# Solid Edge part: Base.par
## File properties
Title: Base
Author: windows
Template: Iso Metric Part.par
Last saved by: windows
Revision: 21
Application: Solid Edge
Username: windows
Density: 886,000 kg/m^3
Accuracy: 0,990
Material: Polyethylene, low density
Face Style: Blue
Fill Style: ANSI34(Plastic)
Virtual Style: ANSI34(Plastic)
Grouping: Non-metals\Plastics
LibraryName: Materials
Coef. of Thermal Exp: 0.00016
Thermal Conductivity: 3.9
Specific Heat: 2219.0
Modulus of Elasticity: 144789897.0
Poisson's Ratio: 0.35
Yield Stress: 9652659.8
Ultimate Stress: 0.0
Elongation: 0.0
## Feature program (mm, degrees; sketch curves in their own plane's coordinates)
swept protrusion "Protrusion_1"
sketch for "ExtrudedCutout_1" plane through (0, 0, 0) normal (0, 0, 1) x-axis (1, 0, 0)
extrude "ExtrudedCutout_1" cut finite 36.5507 along -normal
sketch used by "Protrusion_1" plane through (148.6392, 0, 45.0365) normal (0.570057, 0, 0.821605) x-axis (0, 1, 0)
extrude "Protrusion_1" add finite 77.0756 along +normal
sketch for "ExtrudedCutout_2" plane through (157.5009, 0, 46.9978) normal (0, 0, -1) x-axis (0, -1, 0)
extrude "ExtrudedCutout_2" cut finite 108.6577 along -normal
sketch for "Protrusion_2" plane through (156.0857, 0, 46.9978) normal (0, 0, 1) x-axis (0, 1, 0)
  line (-5, -6.0857) -> (-5, 6.0857)
  line (-5, 6.0857) -> (5, 6.0857)
  line (5, 6.0857) -> (5, -6.0857)
  line (5, -6.0857) -> (-5, -6.0857)
extrude "Protrusion_2" add finite 23 along +normal
fillet "Round_1" radius 2
fillet "Round_2" radius 2
fillet "Round_3" radius 5
fillet "Round_4" radius 5
rib "Rib_1"  Thickness = 3 mm
fillet "Round_5" radius 1
sketch used by "Cutout_3" plane through (77.5395, 0, 57) normal (0, 0, 1) x-axis (0, 1, 0)
  line (-25, -23.8999) -> (25, -23.8999)
  line (25, -23.8999) -> (25, 26.1001)
  line (25, 26.1001) -> (-25, 26.1001)
  line (-25, 26.1001) -> (-25, -23.8999)
  line (-35.5538, 44.0098) -> (-15.5538, 44.0098)
  line (-15.5538, 44.0098) -> (-15.5538, 64.0098)
  line (-15.5538, 64.0098) -> (-35.5538, 64.0098)
  line (-35.5538, 64.0098) -> (-35.5538, 44.0098)
extrude "Cutout_3" cut finite 5 symmetric
sketch for "Cutout_4" plane through (76.0856, -50.2879, 25.7796) normal (0.036015, -0.999292, 0.0109) x-axis (-0.999351, -0.036018, 0)
extrude "Cutout_4" cut finite 20 symmetric
sketch for "unnamed Protrusion 1" #1 plane through (13.8042, -42.9841, 25.7796) normal (0.19183, 0.981385, -0.009162) x-axis (0.981427, -0.191838, 7e-06)
sketch for "unnamed Protrusion 1" #2 plane through (13.8042, -42.9841, 25.7796) normal (0.19183, 0.981385, -0.009162) x-axis (0.981427, -0.191838, 7e-06)
extrude "unnamed Protrusion 1" add finite 3 along -normal
mirror "unnamed Mirror 1" of "unnamed Protrusion 1", "Cutout_4"
pattern "unnamed Pattern 1"
sketch used by "Protrusion_4" plane through (0, 0, 28.5) normal (-1, 0, 0) x-axis (0, -1, 0)
extrude "Protrusion_4" add finite 0.01 along +normal
sketch for "unnamed Protrusion 2" plane through (73.5, -1.9531, 62) normal (0, 0, 1) x-axis (0, 1, 0)
  circle centre (-42.0768, 67.8235) radius 1
extrude "unnamed Protrusion 2" add finite 7 along +normal
pattern "Pattern_1" of "unnamed Protrusion 2" along a curve  XDirCount = 8; XDirSpacing = 20 mm
extrude "unnamed Protrusion 3" add finite 7
extrude "unnamed Protrusion 4" add finite 7
extrude "unnamed Protrusion 5" add finite 7
extrude "unnamed Protrusion 6" add finite 7
extrude "unnamed Protrusion 7" add finite 7
extrude "unnamed Protrusion 8" add finite 7
extrude "unnamed Protrusion 9" add finite 7
replace surface "unnamed ReplaceSurface 1"
swept protrusion "Protrusion_2"
mirror "unnamed Mirror 2" of "Protrusion_2", "unnamed ReplaceSurface 1", "Pattern_1", "unnamed Protrusion 2" about plane through (0, 0, 0) normal (0, -1, 0)
extrude "unnamed Protrusion 10" add finite 7
extrude "unnamed Protrusion 11" add finite 7
extrude "unnamed Protrusion 12" add finite 7
extrude "unnamed Protrusion 13" add finite 7
extrude "unnamed Protrusion 14" add finite 7
extrude "unnamed Protrusion 15" add finite 7
extrude "unnamed Protrusion 16" add finite 7
extrude "unnamed Protrusion 17" add finite 7
replace surface "unnamed ReplaceSurface 2"
swept protrusion "unnamed SweptProtrusion 1"
replace surface "unnamed ReplaceSurface 3"
make body feature "unnamed MakeBodyFeature 1"
logasc func "Lip_1"  LipOrGrooveWidth = 5 mm; LipOrGrooveHeight = 5 mm
logasc func "Lip_2"  LipOrGrooveWidth = 5 mm; LipOrGrooveHeight = 5 mm
mirror "unnamed Mirror 3" of "Lip_1" about plane through (0, 0, 0) normal (0, -1, 0)
logasc func "unnamed LOGAscFunc 1"
mirror "unnamed Mirror 4" of "Lip_2" about plane through (0, 0, 0) normal (0, -1, 0)
logasc func "unnamed LOGAscFunc 2"
logasc func "Lip_3"  LipOrGrooveWidth = 5 mm; LipOrGrooveHeight = 5 mm
logasc func "Lip_4"  LipOrGrooveWidth = 5 mm; LipOrGrooveHeight = 5 mm
logasc func "Lip_5"  LipOrGrooveWidth = 5 mm; LipOrGrooveHeight = 5 mm
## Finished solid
Body 1: solid body, 225 faces, 551 edges, 320 vertices.
  Faces by surface: plane 121, cylinder 36, blend 26, spline 17, swept 13, sphere 8, offset 4
  Edges by curve: line 222, intersection 173, circle 62, curve on surface 48, spline 30, ellipse 16
Body 2: solid body, 6 faces, 12 edges, 8 vertices.
  Faces by surface: plane 3, spline 3
  Edges by curve: line 7, spline 3, curve on surface 2
Bounding box of the edges (mm; curved faces can reach further): 167.171 x 111.081 x 72.879, from (-5, -55.5107, 0) to (162.1713, 55.5698, 72.8789).
Cylindrical faces by radius (mm): R1 x21, R2 x14, R5 x1
Spherical faces by radius (mm): R2 x8
Planar faces by outward normal: +x 7, +y 12, +z 29, -x 18, -y 11, -z 25, oblique 22
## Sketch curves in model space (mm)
circle centre (0.839, -44.0299, 70.3789) radius 2.5
spline (0.839, -43.2544, 69) -> (79.0298, -52.8427, 69) -> (142.7309, -10.6922, 69)
circle centre (73.5856, -70, 25.7796) radius 2.5
circle centre (73.5856, -70, 25.7796) radius 30
circle centre (24.1993, -70, 25.7796) radius 10
spline (150, 0, 69.9978) -> (139.141, 0, 61.4596) -> (129.4978, 0, 52)
circle centre (5.6765, -44.0299, 62) radius 1
circle centre (23.8042, -70, 25.7796) radius 7.5
circle centre (23.8042, -70, 25.7796) radius 10
spline (0, -14.3048, 43.2446) -> (0, -14.3048, 46.3134) -> (0, -14.3048, 49.3822)
spline (0, -16.0893, 43.2446) -> (0, -15.1971, 43.2446) -> (0, -14.3048, 43.2446)
spline (0, -16.0893, 46.6217) -> (0, -16.0893, 44.9331) -> (0, -16.0893, 43.2446)
spline (0, -18.3802, 43.2446) -> (0, -17.2348, 44.9331) -> (0, -16.0893, 46.6217)
spline (0, -20.1688, 43.2446) -> (0, -19.2745, 43.2446) -> (0, -18.3802, 43.2446)
spline (0, -20.1688, 49.3822) -> (0, -20.1688, 46.3134) -> (0, -20.1688, 43.2446)
spline (0, -18.3802, 49.3822) -> (0, -19.2745, 49.3822) -> (0, -20.1688, 49.3822)
spline (0, -18.3802, 45.9887) -> (0, -18.3802, 47.6855) -> (0, -18.3802, 49.3822)
spline (0, -16.073, 49.3822) -> (0, -17.2266, 47.6855) -> (0, -18.3802, 45.9887)
spline (0, -14.3048, 49.3822) -> (0, -15.1889, 49.3822) -> (0, -16.073, 49.3822)
spline (0, -10.7602, 49.4884) -> (0, -11.4646, 49.4884) -> (0, -12.1691, 49.4884)
spline (0, -8.6612, 47.8427) -> (0, -9.9185, 48.4459) -> (0, -10.7602, 49.4884)
spline (0, -8.6612, 46.442) -> (0, -8.6612, 47.1424) -> (0, -8.6612, 47.8427)
spline (0, -10.4499, 47.3363) -> (0, -9.6079, 46.8007) -> (0, -8.6612, 46.442)
spline (0, -10.4499, 43.2446) -> (0, -10.4499, 45.2905) -> (0, -10.4499, 47.3363)
spline (0, -12.1691, 43.2446) -> (0, -11.3095, 43.2446) -> (0, -10.4499, 43.2446)
spline (0, -12.1691, 49.4884) -> (0, -12.1691, 46.3665) -> (0, -12.1691, 43.2446)
spline (0, -0.4777, 43.2446) -> (0, -0.4777, 46.3134) -> (0, -0.4777, 49.3822)
spline (0, -2.0295, 43.2446) -> (0, -1.2536, 43.2446) -> (0, -0.4777, 43.2446)
spline (0, -2.0295, 47.9244) -> (0, -2.0295, 45.5845) -> (0, -2.0295, 43.2446)
spline (0, -3.226, 43.2446) -> (0, -2.6277, 45.5845) -> (0, -2.0295, 47.9244)
spline (0, -4.6307, 43.2446) -> (0, -3.9284, 43.2446) -> (0, -3.226, 43.2446)
spline (0, -5.8272, 47.9244) -> (0, -5.229, 45.5845) -> (0, -4.6307, 43.2446)
spline (0, -5.8272, 43.2446) -> (0, -5.8272, 45.5845) -> (0, -5.8272, 47.9244)
spline (0, -7.379, 43.2446) -> (0, -6.6031, 43.2446) -> (0, -5.8272, 43.2446)
spline (0, -7.379, 49.3822) -> (0, -7.379, 46.3134) -> (0, -7.379, 43.2446)
spline (0, -4.8921, 49.3822) -> (0, -6.1355, 49.3822) -> (0, -7.379, 49.3822)
spline (0, -3.9324, 45.6457) -> (0, -4.4123, 47.514) -> (0, -4.8921, 49.3822)
spline (0, -2.9728, 49.3822) -> (0, -3.4526, 47.514) -> (0, -3.9324, 45.6457)
spline (0, -0.4777, 49.3822) -> (0, -1.7253, 49.3822) -> (0, -2.9728, 49.3822)
closed spline through (0, 3.7978, 46.3359), (0, 3.0371, 44.3038), (0, 2.1691, 46.4275), (0, 3.0003, 48.3572)
closed spline through (0, 5.4884, 46.3399), (0, 2.8713, 49.4879), (0, 0.4741, 46.4205), (0, 2.3661, 43.1835), (0, 5.4475, 45.5557)
closed spline through (0, 9.5189, 46.3359), (0, 8.7416, 44.3029), (0, 7.8862, 46.4283), (0, 8.7156, 48.3572)
closed spline through (0, 11.2055, 46.3399), (0, 8.589, 49.4879), (0, 6.1911, 46.4224), (0, 8.0875, 43.1834), (0, 11.1645, 45.5557)
spline (0, 19.0337, 43.2446) -> (0, 19.0337, 46.3134) -> (0, 19.0337, 49.3822)
spline (0, 17.482, 43.2446) -> (0, 18.2579, 43.2446) -> (0, 19.0337, 43.2446)
spline (0, 17.482, 47.9244) -> (0, 17.482, 45.5845) -> (0, 17.482, 43.2446)
spline (0, 16.2855, 43.2446) -> (0, 16.8837, 45.5845) -> (0, 17.482, 47.9244)
spline (0, 14.8848, 43.2446) -> (0, 15.5851, 43.2446) -> (0, 16.2855, 43.2446)
spline (0, 13.6842, 47.9244) -> (0, 14.2845, 45.5845) -> (0, 14.8848, 43.2446)
spline (0, 13.6842, 43.2446) -> (0, 13.6842, 45.5845) -> (0, 13.6842, 47.9244)
spline (0, 12.1325, 43.2446) -> (0, 12.9083, 43.2446) -> (0, 13.6842, 43.2446)
spline (0, 12.1325, 49.3822) -> (0, 12.1325, 46.3134) -> (0, 12.1325, 43.2446)
spline (0, 14.6234, 49.3822) -> (0, 13.3779, 49.3822) -> (0, 12.1325, 49.3822)
spline (0, 15.579, 45.6457) -> (0, 15.1012, 47.514) -> (0, 14.6234, 49.3822)
spline (0, 16.5427, 49.3822) -> (0, 16.0609, 47.514) -> (0, 15.579, 45.6457)
spline (0, 19.0337, 49.3822) -> (0, 17.7882, 49.3822) -> (0, 16.5427, 49.3822)
line (101.4394, 25, 57) -> (51.4394, 25, 57)
line (51.4394, 25, 57) -> (51.4394, -25, 57)
line (51.4394, -25, 57) -> (101.4394, -25, 57)
line (101.4394, -25, 57) -> (101.4394, 25, 57)
line (33.5296, -15.5539, 57) -> (13.5296, -15.5539, 57)
line (13.5296, -15.5539, 57) -> (13.5296, -35.5539, 57)
line (13.5296, -35.5539, 57) -> (33.5296, -35.5539, 57)
line (33.5296, -35.5539, 57) -> (33.5296, -15.5539, 57)
line (150, -1, 57) -> (150, -1, 47)
line (0, -40, 57) -> (0, -40, 0)
line (156.8552, -5, 39.3359) -> (148.6392, -5, 45.0365)
line (148.6392, -5, 45.0365) -> (148.6392, 0, 45.0365)
line (148.6392, 5, 45.0365) -> (148.6392, 0, 45.0365)
line (156.8552, 5, 39.3359) -> (148.6392, 5, 45.0365)
line (156.8552, 0, 39.3359) -> (156.8552, 5, 39.3359)
line (156.8552, 0, 39.3359) -> (156.8552, -5, 39.3359)
line (130, -20, 57) -> (130, -20, 22)
line (120, -32, 57) -> (120, -32, 17)
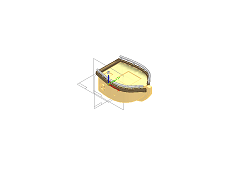
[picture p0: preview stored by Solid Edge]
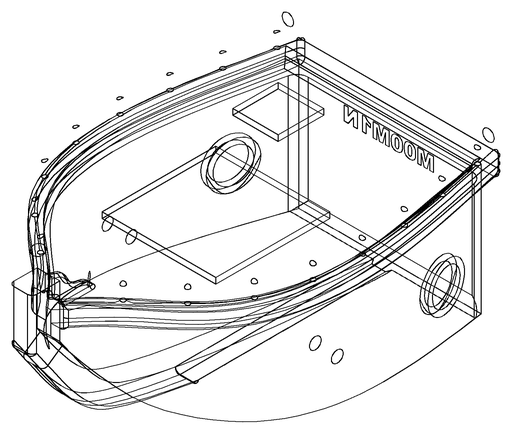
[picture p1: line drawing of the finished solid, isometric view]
